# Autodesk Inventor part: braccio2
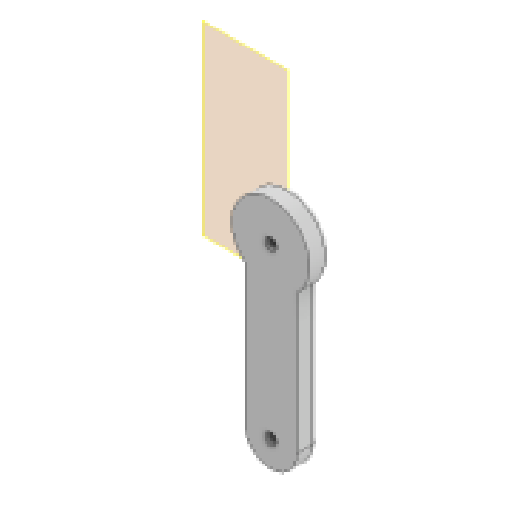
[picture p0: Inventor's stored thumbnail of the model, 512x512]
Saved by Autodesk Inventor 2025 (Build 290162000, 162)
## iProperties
Created: 2025-09
Part Number: braccio2
Material: Generico
Document SubType Name: Modeling
Designer: Ryzen5700u
Density: 1 g/cm^3
Appearance: Default
Author: Ryzen5700u
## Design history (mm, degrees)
node "Piano di lavoro1"
sketch "Schizzo1" dims "d12" = 30
  geometry: L1 (-7, 0.5)-(7, 0.5) reference; L2 (17.956, -49.5)-(17.956, -124.5); L3 (27.956, -60.68)-(7.956, -60.68); L4 (7.956, -60.68)-(7.956, -124.5); L5 (7.956, -124.5)-(27.956, -124.5); L6 (27.956, -124.5)-(27.956, -60.68); L7 (-7, -39.753)-(-7, 0.5) reference; L8 (7, 0.5)-(7, -39.753) reference; C1 r 2.25 at (0, -49.5) reference; A1 r 12 centre (0, -49.5) between (-7, -39.753) and (7, -39.753) reference; 1 further point
  constraints: 10 end point, 2 parallel, 1 horizontal, 1 perpendicular, 1 vertical, 4 other
  dimensions: "d2" = 75 distance of L2.start L2.end; "d3" = 20 distance of L5.end L4.end
extrude "Estrusione1" new body sketch "Schizzo1" distance "d0" = 8; taper "d1" = 0 deg
sketch "Schizzo2"
  geometry: C1 r 2.25 at (-17.956, -114.5) reference; 1 further point
hole "Foro1" sketch "Schizzo2" at (-17.956, -114.5) diameter "d5" = 4.5; stored, may be unused: countersink angle "d9" = 90 deg, drill point angle "d11" = 118 deg; dims "d6" = 6, "d7" = 8, "d8" = 4.6, "d10" = 8
sketch "Schizzo3"
  geometry: C1 r 2.25 at (-17.956, -49.5) reference; 1 further point
hole "Foro2" sketch "Schizzo3" at (-17.956, -49.5) diameter "d13" = 4.5; stored, may be unused: countersink angle "d17" = 90 deg, drill point angle "d19" = 118 deg; dims "d14" = 6, "d15" = 8, "d16" = 4.6, "d18" = 8
sketch "Schizzo6"
  geometry: L1 (-14.478, -67.818)-(-14.478, -99.791); L2 (-14.478, -99.791)-(-19.673, -99.791); L3 (-19.673, -99.791)-(-19.673, -67.818); L4 (-19.673, -67.818)-(-14.478, -67.818); 1 further point
  constraints: 2 other
extrude "Estrusione3" cut sketch "Schizzo6" distance "d23" = 0.2; taper "d24" = 0 deg
fillet "Raccordo3" dims "d25" = 10
fillet "Raccordo4" dims "d26" = 2
node "Solido1"
node "Riferimento1"
node "Riferimento2"
node "Riferimento3"
